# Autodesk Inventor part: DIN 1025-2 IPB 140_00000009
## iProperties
Created: 2006-02
Part Number: DIN 1025-2 IPB 140_00000009
Material: Default
Document SubType Name: Modeling
Designer: 40664
Manufacturer: Standard
Standards Organization: Custom
Stock Number: DIN 1025-2 IPB 140
Mass: 11082.7 g
Surface Area: 20865.2 cm^2
Volume: 11082.7 cm^3
Density: 1 g/cm^3
G_L: 2580.000 mm
G_W: 140.000 mm
G_H: 140.000 mm
AFG_Item: IPB 140
CSToolsMass: 11.0
CSToolsVolume: 11082691.0
CSToolsArea: 20865.0
Author: 40664
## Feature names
1. AFG_Detailed_DIN 1025-2 IPB 140_00000009 [Extrusion]
2. AFG_Simplified_DIN 1025-2 IPB 140_00000009 [Extrusion]
